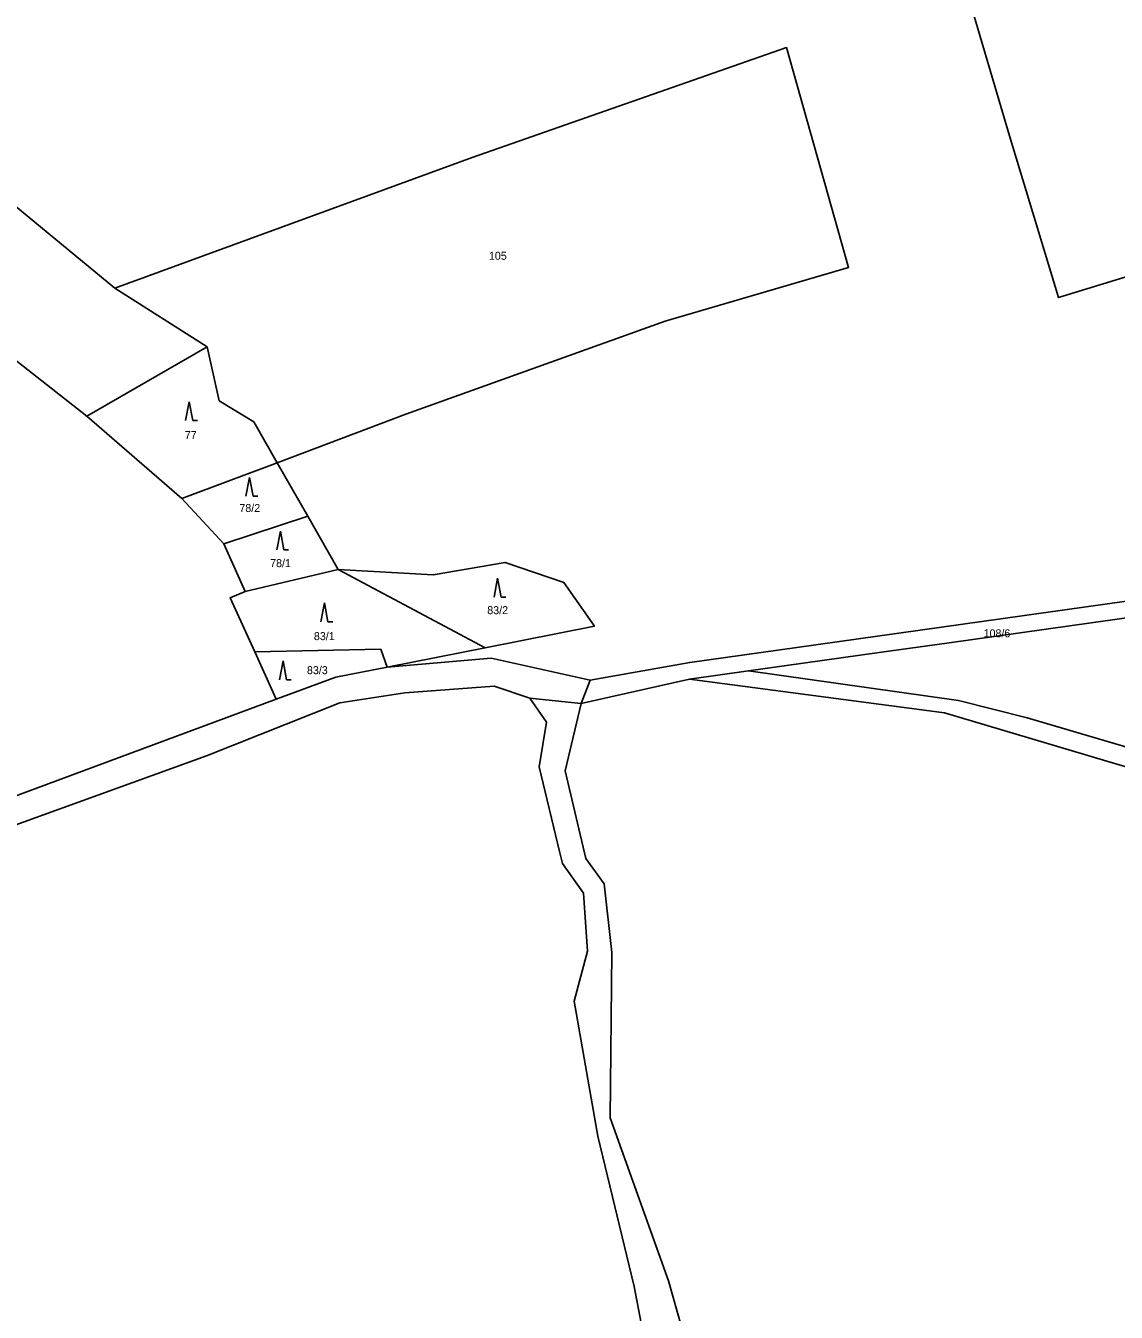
# Model space of a CAD drawing. Extents: x -779723 to -777378, y -1011169 to -1009297.
# Drawn here: x -778661.4 to -778429.6, y -1010177.3 to -1009904 of the extents above; entities that cross this region are included whole.
import ezdxf

# ---------------------------------------------------------------- set-up
doc = ezdxf.new("R2010")
doc.units = 0
for name, color, linetype in [('Hranice parcel', 7, 'Continuous'), ('Parcelní čísla', 7, 'Continuous'), ('Značky kultur', 7, 'Continuous')]:
    doc.layers.add(name, color=color, linetype=linetype)

msp = doc.modelspace()

# ---------------------------------------------------------------- linework, layer by layer
at = {"layer": 'Hranice parcel'}
for p, q in [((-778622.81, -1009972.22), (-778642.47, -1009959.73)), ((-778670.06, -1009969.95), (-778648.43, -1009986.95)), ((-778648.43, -1009986.95), (-778622.81, -1009972.22)), ((-778648.43, -1009986.95), (-778628.19, -1010004.45)), ((-778628.19, -1010004.45), (-778607.95, -1009996.84)), ((-778601.46, -1010008.2), (-778607.95, -1009996.84)), ((-778628.19, -1010004.45), (-778619.27, -1010014.08)), ((-778601.46, -1010008.2), (-778619.27, -1010014.08)), ((-778594.98, -1010019.53), (-778601.46, -1010008.2)), ((-778619.27, -1010014.08), (-778614.73, -1010024.15)), ((-778614.73, -1010024.15), (-778594.98, -1010019.53)), ((-778563.77, -1010036.13), (-778594.98, -1010019.53)), ((-778608.15, -1010047.05), (-778612.72, -1010037)), ((-778584.59, -1010040.25), (-778563.77, -1010036.13)), ((-778543.3, -1010047.94), (-778520.34, -1010042.8)), ((-778541.4, -1010042.99), (-778543.3, -1010047.94)), ((-778520.34, -1010042.8), (-778507.76, -1010041.04)), ((-778543.3, -1010047.94), (-778554.23, -1010046.82))]:
    msp.add_line(p, q, dxfattribs=at)
for points in [[(-778424.79, -1009797.42), (-778418.38, -1009822.49), (-778397.98, -1009883.84), (-778390.73, -1009908.28), (-778380.68, -1009942.03), (-778409.93, -1009951.93), (-778441.85, -1009961.74), (-778452.32, -1009927.34), (-778461.29, -1009896.85), (-778477.95, -1009840.27)], [(-778642.47, -1009959.73), (-778566.52, -1009931.95), (-778499.66, -1009908.62), (-778486.49, -1009955.32), (-778525.48, -1009966.76), (-778580.61, -1009986.47), (-778607.95, -1009996.84)], [(-778642.47, -1009959.73), (-778670.88, -1009936.37), (-778699.18, -1009922.39)], [(-778607.95, -1009996.84), (-778612.91, -1009988.16), (-778620.25, -1009983.66), (-778622.81, -1009972.22)], [(-778541.4, -1010042.99), (-778520.25, -1010039.26), (-778497.51, -1010036.07), (-778348.28, -1010015.11)], [(-778563.77, -1010036.13), (-778540.53, -1010031.53), (-778547, -1010022.25), (-778559.52, -1010017.99), (-778574.79, -1010020.66), (-778594.98, -1010019.53)], [(-778507.76, -1010041.04), (-778479.97, -1010037.14), (-778465.13, -1010035.06), (-778347.45, -1010018.54)], [(-778612.72, -1010037), (-778617.96, -1010025.49), (-778614.73, -1010024.15)], [(-778612.72, -1010037), (-778585.92, -1010036.44), (-778584.59, -1010040.25)], [(-778584.59, -1010040.25), (-778595.49, -1010042.35), (-778608.15, -1010047.05)], [(-778584.59, -1010040.25), (-778562.47, -1010038.37), (-778541.4, -1010042.99)], [(-777915.32, -1010130.76), (-777965.67, -1010115.09), (-777984.81, -1010115.73), (-777999.17, -1010116.04), (-778039.22, -1010109.98), (-778074.01, -1010110.38), (-778103.23, -1010113.41), (-778121.64, -1010116.47), (-778151.12, -1010114.44), (-778174.14, -1010109.8), (-778185.39, -1010108.53), (-778237.09, -1010105.96), (-778294.76, -1010098.57), (-778302.43, -1010096.77), (-778365.7, -1010080.27), (-778423.7, -1010062.57), (-778466.13, -1010049.97), (-778520.34, -1010042.8)], [(-778507.76, -1010041.04), (-778463.16, -1010047.36), (-778448.54, -1010051.05), (-778413.41, -1010061.34), (-778360.73, -1010076.84), (-778296.58, -1010094.47), (-778291.4, -1010095.84), (-778239.95, -1010101.4), (-778180.65, -1010104.69), (-778145.9, -1010109.73), (-778118.76, -1010110.86), (-778075.46, -1010104.51), (-778036.74, -1010105.05), (-778006.46, -1010110.09), (-777991.99, -1010110.55), (-777964.85, -1010110.4), (-777924.86, -1010123.86)], [(-778554.23, -1010046.82), (-778561.81, -1010044.31), (-778580.85, -1010045.72), (-778594.64, -1010047.86), (-778622.94, -1010059.11), (-778684.92, -1010081.46), (-778712.5, -1010092.84), (-778729.23, -1010099), (-778782.95, -1010115.6), (-778810.44, -1010123.41)], [(-778981.44, -1010170.24), (-778960.05, -1010166.44), (-778917.58, -1010149.52), (-778869.36, -1010132.88), (-778766.08, -1010103.5), (-778721.06, -1010087.16), (-778695.97, -1010079.62), (-778608.15, -1010047.05)], [(-778500.81, -1010301.69), (-778513.85, -1010270.13), (-778526.89, -1010224.31), (-778522.27, -1010222.95), (-778532.06, -1010171.83), (-778539.76, -1010139.89), (-778544.84, -1010111.19), (-778541.98, -1010100.57), (-778542.87, -1010088.3), (-778547.31, -1010081.95), (-778547.93, -1010079.4), (-778552.26, -1010061.45), (-778550.67, -1010051.95), (-778554.23, -1010046.82)], [(-778543.3, -1010047.94), (-778546.71, -1010062.28), (-778542.32, -1010080.9), (-778538.43, -1010086.26), (-778536.83, -1010100.87), (-778537.2, -1010135.97), (-778524.77, -1010170.64), (-778510.96, -1010219.51), (-778493.25, -1010262.91), (-778502.97, -1010266.15), (-778491.82, -1010293.76)]]:
    msp.add_lwpolyline(points, dxfattribs=at)
at = {"layer": 'Značky kultur'}
for p, q in [((-778626.66, -1009983.86), (-778627.41, -1009987.86)), ((-778625.91, -1009987.86), (-778626.66, -1009983.86)), ((-778625.91, -1009987.86), (-778624.91, -1009987.86)), ((-778613.84, -1009999.94), (-778614.59, -1010003.94)), ((-778613.09, -1010003.94), (-778613.84, -1009999.94)), ((-778613.09, -1010003.94), (-778612.09, -1010003.94)), ((-778607.26, -1010011.36), (-778608.01, -1010015.36)), ((-778606.51, -1010015.36), (-778607.26, -1010011.36)), ((-778606.51, -1010015.36), (-778605.51, -1010015.36)), ((-778561.1, -1010021.37), (-778561.85, -1010025.37)), ((-778560.35, -1010025.37), (-778561.1, -1010021.37)), ((-778597.9, -1010026.61), (-778598.65, -1010030.61)), ((-778597.15, -1010030.61), (-778597.9, -1010026.61)), ((-778560.35, -1010025.37), (-778559.35, -1010025.37)), ((-778597.15, -1010030.61), (-778596.15, -1010030.61)), ((-778606.71, -1010038.92), (-778607.46, -1010042.92)), ((-778605.96, -1010042.92), (-778606.71, -1010038.92)), ((-778605.96, -1010042.92), (-778604.96, -1010042.92))]:
    msp.add_line(p, q, dxfattribs=at)

# ---------------------------------------------------------------- texts
at = {"layer": 'Parcelní čísla'}
for s, p in [('105', (-778562.95, -1009953.7)), ('77', (-778627.59, -1009991.78)), ('78/2', (-778615.99, -1010007.29)), ('78/1', (-778609.45, -1010019)), ('83/2', (-778563.3, -1010028.99)), ('108/6', (-778457.8, -1010033.91)), ('83/1', (-778600.15, -1010034.51)), ('83/3', (-778601.62, -1010041.74))]:
    msp.add_text(s, height=1.7, dxfattribs=at).set_placement(p)

doc.saveas('drawing.dxf')
